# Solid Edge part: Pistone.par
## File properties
Author: Administrator
Template: Normal.par
Last saved by: Luca
Revision: 25
Application: Solid Edge
Precisione: 0.990
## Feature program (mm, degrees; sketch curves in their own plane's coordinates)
sketch for "unnamed Protrusion 1" plane through (0, 0, 0) normal (0, 0, 1) x-axis (1, 0, 0)
  circle centre (0, 0) radius 47.7
extrude "unnamed Protrusion 1" add finite 100 along +normal
sketch for "unnamed RevolvedCutout 1" plane through (0, 0, 0) normal (1, 0, 0) x-axis (0, 1, 0)
  circle centre (-22.7, 93) radius 10
  dimension (linear) = 22.7
revolve "unnamed RevolvedCutout 1" cut full turn 360 deg
sketch for "ExtrudedCutout_1" plane through (0, 0, 100) normal (0, 0, 1) x-axis (-1, 0, 0)
  circle centre (0, 0) radius 18.3176
extrude "ExtrudedCutout_1" cut finite 10 along -normal
sketch for "ExtrudedCutout_3" plane through (0, 0, 0) normal (0, 0, -1) x-axis (0, -1, 0)
  line (-29.1333, 27.7) -> (29.1333, 27.7)
  arc centre (0, 0) radius 40.2 from (29.1333, 27.7) to (29.1333, -27.7) cw
  line (-29.1333, -27.7) -> (29.1333, -27.7)
extrude "ExtrudedCutout_3" cut finite 70 along -normal
sketch for "unnamed Cutout 1" plane through (0, 0, 0) normal (1, 0, 0) x-axis (0, 1, 0)
  circle centre (0, 42) radius 16
extrude "unnamed Cutout 1" cut through
sketch for "ExtrudedCutout_5" #1 plane through (0, 0, 0) normal (0, -1, 0) x-axis (1, 0, 0)
  arc centre (29, 0) radius 13 from (16, 0) to (29, 13) cw
  line (29, 13) -> (48.7494, 13)
  line (48.7494, 13) -> (48.7494, -5.6705)
  line (48.7494, -5.6705) -> (16, -5.6705)
  line (16, -5.6705) -> (16, 0)
sketch for "ExtrudedCutout_5" #2 plane through (0, 0, 0) normal (0, -1, 0) x-axis (1, 0, 0)
  arc centre (-29, 0) radius 13 from (-16, 0) to (-29, 13) ccw
  line (-29, 13) -> (-48.7494, 13)
  line (-48.7494, 13) -> (-48.7494, -5.6705)
  line (-48.7494, -5.6705) -> (-16, -5.6705)
  line (-16, -5.6705) -> (-16, 0)
extrude "ExtrudedCutout_5" cut finite 139.7 symmetric
sketch for "unnamed RevolvedCutout 2" #1 plane through (0, 0, 0) normal (1, 0, 0) x-axis (0, 1, 0)
sketch for "unnamed RevolvedCutout 2" #2 plane through (0, 0, 0) normal (1, 0, 0) x-axis (0, 1, 0)
sketch for "unnamed RevolvedCutout 2" #3 plane through (0, 0, 0) normal (1, 0, 0) x-axis (0, 1, 0)
revolve "unnamed RevolvedCutout 2" cut full turn 360 deg
sketch for "unnamed Hole 1" plane through (38.35, 0, 13) normal (0, 0, -1) x-axis (0, 1, 0)
hole "unnamed Hole 1" through
pattern "unnamed Pattern 1" of "unnamed Hole 1"
mirror "unnamed Mirror 1" of "unnamed Pattern 1" about plane through (0, 0, 0) normal (0, -1, 0)
hole "unnamed Hole 2" through
mirror "unnamed Mirror 2" of "unnamed Pattern 1", "unnamed Mirror 1" about plane through (0, 0, 0) normal (1, 0, 0)
sketch for "unnamed Hole 3"
  line (-55.5603, 67) -> (-42.7, 67)
  line (-42.7, 67) -> (-42.7, 61)
  line (-42.7, 61) -> (-55.5603, 61)
  line (-55.5603, 61) -> (-55.5603, 67)
hole "unnamed Hole 3" through
hole "unnamed Hole 4" through
fillet "Rotondo_4" radius 10
Other named dimensions: "Foro_1": Diameter = 5 mm
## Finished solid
Body 1: solid body, 37 faces, 65 edges, 24 vertices.
  Faces by surface: cylinder 19, plane 15, torus 3
  Edges by curve: circle 31, intersection 18, line 16
Bounding box of the edges (mm; curved faces can reach further): 95.400 x 95.400 x 100.000, from (-47.7, -47.7, 0) to (47.7, 47.7, 100).
Cylindrical faces by radius (mm): R2.5 x4, R10 x2, R13 x2, R16 x2, R40.2 x2, R42.7 x3, R47.7 x4
Toroidal faces (ring radius, tube radius in mm): R22.7 r10 x1, R30.2 r10 x2
Planar faces by outward normal: +x 1, +z 5, -x 1, -z 8
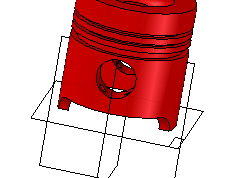
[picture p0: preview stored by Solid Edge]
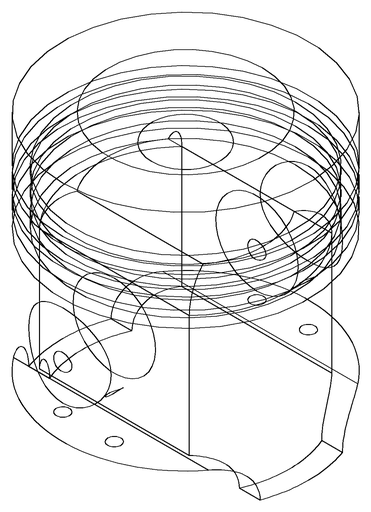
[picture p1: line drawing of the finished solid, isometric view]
